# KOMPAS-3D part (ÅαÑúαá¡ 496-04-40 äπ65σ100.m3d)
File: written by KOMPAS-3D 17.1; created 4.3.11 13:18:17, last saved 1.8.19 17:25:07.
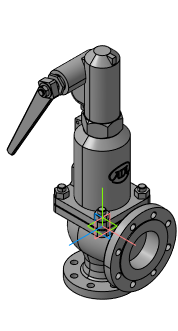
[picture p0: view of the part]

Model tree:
1. Плоскость XY
2. Плоскость ZX
3. Плоскость ZY
4. Ось X
5. Ось Y
6. Ось Z
7. Начало координат
8. Операция без истории:3  (with: Сечение модели:1)

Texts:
  Точка начала. Х
  Точка начала. Y
  Точка начала. Z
